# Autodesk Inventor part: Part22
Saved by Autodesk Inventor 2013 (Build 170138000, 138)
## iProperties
Created: 2012-07
Part Number: Part22
Material: Generic
Document SubType Name: Modeling
Designer: Paul
Density: 1 g/cm^3
Author: Paul
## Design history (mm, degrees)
node "User Library-Arduino Mega.SAT1"
body "Solid1"
node "Base1"
